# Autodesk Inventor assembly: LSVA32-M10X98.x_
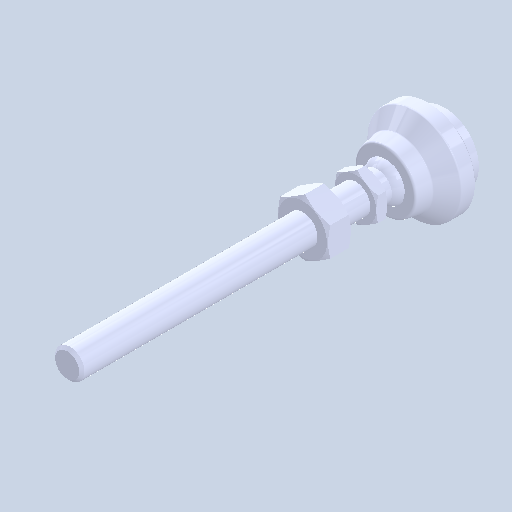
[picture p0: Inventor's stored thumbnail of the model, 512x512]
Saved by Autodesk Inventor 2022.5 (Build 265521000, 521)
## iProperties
Created: 2024-08
Part Number: LSVA32-M10X98.x_
Document SubType Name: Assembly
Designer: ImaoCorp
Author: ImaoCorp
Sending System: SOLIDWORKS 2022-2022290
MC: AMD64
MC_MODEL: Intel64 Family 6 Model 60 Stepping 3, GenuineIntel
OS: Windows_NT
FRU: Parasolid Version 33.1, build 260,  4-25-2022
FORMAT: text
GUISE: transmit
KEY: FILELSVA32-M10X98.x_t
DATE: Fri Aug 23 16:06:28 2024
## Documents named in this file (4)
- X:\14_SW2022-Inv2022\06_2024-10新製品(SME)\ELS_データ\l\lsva32-m10x98\LSVA32-M10X98.x_.iam
- X:\14_SW2022-Inv2022\06_2024-10新製品(SME)\ELS_データ\l\lsva32-m10x98\LSVA32-M10X98_01.ipt
- X:\14_SW2022-Inv2022\06_2024-10新製品(SME)\ELS_データ\l\lsva32-m10x98\LSVA32-M10X98_02.ipt
- X:\14_SW2022-Inv2022\06_2024-10新製品(SME)\ELS_データ\l\lsva32-m10x98\LSVA32-M10X98_03.ipt
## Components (3 placed, 3 different names)
1. LSVA32-M10X98_01
2. LSVA32-M10X98_02
3. LSVA32-M10X98_03
